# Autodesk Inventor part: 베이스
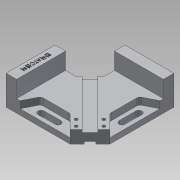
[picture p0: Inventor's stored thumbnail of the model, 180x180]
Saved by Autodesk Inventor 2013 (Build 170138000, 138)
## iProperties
Created: 2019-04
Part Number: 베이스
Material: 알루미늄 6061
Document SubType Name: Modeling
Designer: Administrator
Density: 2.71 g/cm^3
Mass: 602.17 g
Surface Area: 427.402 cm^2
Volume: 222.203 cm^3
Author: Administrator
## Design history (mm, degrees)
sketch "스케치1"
  geometry: L1 (-60, -60)-(31.716, -60); L2 (60, -60)-(60, -31.716); L3 (60, 60)-(-10, 60); L4 (-60, 60)-(-60, 10); L5 (-60, -60)-(60, 60); L6 (60, -60)-(-60, 60); L7 (-60, 10)-(-29.806, 10); L8 (-10, 10)-(-10, 29.806); L9 (-29.806, 10)-(-9.829, 29.977); L10 (31.716, -60)-(60, -31.716); L11 (-60, 10)-(-60, -60); L12 (-10, 60)-(-60, 60); L13 (-29.806, 10)-(-10, 10); L14 (-10, 29.806)-(-10, 60); L15 (31.716, -60)-(60, -60); L16 (60, -31.716)-(60, 60); 1 further point
  constraints: 32 end point, 9 parallel, 5 perpendicular, 4 horizontal, 2 midpoint, 2 point on line, 2 vertical
  dimensions: "d0" = 120 distance of L4.start L3.start; "d1" = 120 distance of L3.start L2.start; "d2" = 50 distance of L8.start L3.end; "d3" = 93 distance between parallel lines of L9 L10; "d4" = 20 distance from line of L10 L2.start
extrude "돌출1" new body sketch "스케치1" distance "d5" = 42; taper "d6" = 0 deg
sketch "스케치2"
  geometry: L1 (-60, -60)-(31.716, -60) reference; L2 (31.716, -60)-(60, -31.716) reference; L3 (-10, 29.806)-(-29.806, 10) reference; L4 (-60, 10)-(-60, -60) reference; L5 (-40, -60)-(-30, -40); L6 (-30, -40)-(11.716, -40); L7 (-20, -54.5)-(4, -54.5); L8 (-20, -45.5)-(4, -45.5); L9 (45.858, -45.858)-(0, 0); L10 (11.716, -40)-(31.716, -60); A1 r 4.5 centre (-20, -50) between (-20, -45.5) and (-20, -54.5); A2 r 4.5 centre (4, -50) between (4, -54.5) and (4, -45.5); 2 further points
  constraints: 12 end point, 4 point on circle, 4 tangent, 2 centre point, 2 point on line, 1 equal radius, 1 horizontal, 1 horizontal alignment, 1 midpoint, 1 parallel, 1 perpendicular
  dimensions: "d8" = 20 distance from line of L5.start L4; "d9" = 30 distance from line of L5.end L4; "d10" = 9 diameter of A1; "d11" = 40 distance from line of A1.centre L4; "d12" = 24 distance of A2.centre A1.centre; "d13" = 10 distance from line of L1 A1.centre; "d14" = 20 distance between parallel lines of L1 L6; "d15" = 20 distance between parallel lines of L10 L9; "d16" = 6 distance from line of point (31.716, -51.515) L2; "d17" = 12 distance of point (23.23, -43.029) point (31.716, -51.515); "d18" = 14 distance from line of point (31.716, -51.515) L9; "d19" = 14 distance from line of L9 point (23.23, -43.029)
extrude "돌출2" cut sketch "스케치2" distance "d20" = 34; taper "d21" = 0 deg
extrude "돌출3" cut sketch "스케치2" stored distance "d22" = 34; taper "d23" = 0 deg
sketch "스케치3"
  geometry: L1 (11.716, -40)-(31.716, -60) reference; L2 (31.716, -60)-(60, -31.716) reference; L3 (-10, 29.806)-(-29.806, 10) reference; L4 (-29.806, 10)-(-60, 10) reference; L5 (-60, 10)-(-60, -60) reference; L6 (-60, -60)-(-40, -60) reference; L7 (-40, -60)-(-30, -40) reference; L8 (-30, -40)-(11.716, -40) reference; L9 (-45, -60)-(-45, 10); L10 (-19.903, 19.903)-(45.858, -45.858); 1 further point
  constraints: 4 end point, 2 midpoint, 2 point on line, 1 vertical
  dimensions: "d24" = 15 distance between parallel lines of L9 L5
extrude "돌출4" cut sketch "스케치3" distance "d25" = 24; taper "d26" = 0 deg
sketch "스케치4"
  geometry: L1 (10, 29.806)-(29.806, 10) reference; L2 (-31.716, -60)-(-60, -31.716) reference; L3 (-45.858, -45.858)-(19.903, 19.903); L4 (-31.716, -51.515)-(-23.23, -43.029); 2 further points
  constraints: 4 end point, 4 midpoint, 1 parallel
  dimensions: "d27" = 6 distance from line of L4.start L2; "d28" = 12 distance of L4.start L4.end; "d29" = 14 distance between parallel lines of L4 L3
hole "구멍1" sketch "스케치4" diameter "d31" = 4.5; stored, may be unused: countersink angle "d35" = 90 deg, drill point angle "d37" = 118 deg; dims "d32" = 6, "d33" = 8, "d34" = 10, "d36" = 8
sketch "스케치5"
  geometry: L1 (10, 29.806)-(29.806, 10) reference; L2 (-31.716, -60)-(-60, -31.716) reference; L3 (-41.615, -50.101)-(24.146, 15.66); L4 (-50.101, -41.615)-(15.66, 24.146); 1 further point
  constraints: 4 end point, 4 point on line, 1 parallel, 1 perpendicular
  dimensions: "d38" = 12 distance between parallel lines of L4 L3; "d39" = 6 distance from line of L4 point (0, 0)
extrude "돌출5" cut sketch "스케치5" distance "d40" = 3.5; taper "d41" = 0 deg
sketch "스케치6"
  geometry: L1 (31.716, -60)-(11.716, -40) reference; L2 (60, -31.716)-(31.716, -60) reference; L3 (40, -11.716)-(60, -31.716) reference; L4 (40, 30)-(40, -11.716) reference; L5 (60, 40)-(40, 30) reference; L6 (60, 45)-(60, 40) reference; L7 (60, 45)-(-10, 45) reference; L8 (-10, 29.806)-(-10, 45) reference; L9 (-29.806, 10)-(-10, 29.806) reference; L10 (-45, 10)-(-29.806, 10) reference; L11 (-45, -60)-(-45, 10) reference; L12 (-40, -60)-(-45, -60) reference; L13 (-30, -40)-(-40, -60) reference; L14 (11.716, -40)-(-30, -40) reference; C1 r 2.25 at (31.716, -51.515) reference; C2 r 2.25 at (23.23, -43.029) reference; 1 further point
node "작업 평면1"
sketch "스케치7"
  geometry: L1 (60, -31.716)-(31.716, -60) reference; L2 (-29.806, 10)-(-10, 29.806) reference; L3 (-25.56, 14.246)-(40.201, -51.515); L4 (-14.246, 25.56)-(51.515, -40.201); 1 further point
  constraints: 4 end point, 4 point on line, 2 perpendicular
  dimensions: "d42" = 16 distance between parallel lines of L4 L3; "d43" = 8 distance from line of point (0, 0) L4
extrude "돌출6" cut sketch "스케치7" distance "d44" = 3.5; taper "d45" = 0 deg
fillet "모깎기1" dims "d46" = 5
sketch "스케치8"
  geometry: L1 (-45, 10)-(-60, 10) reference; L2 (-60, 10)-(-60, -60) reference; 2 further points
  constraints: 1 other
  dimensions: "d47" = 35 distance from line of L1 point (-52.5, -25); "d48" = 7.5 distance from line of L2 point (-52.5, -25)
feature "엠보싱1" sketch "스케치8" dims "d0" = 120, "d1" = 120, "d2" = 50, "d3" = 93, "d4" = 20, "d49" = 0.5, "d50" = 0
node "솔리드1"
mirror "대칭1"
mirror "대칭2"
